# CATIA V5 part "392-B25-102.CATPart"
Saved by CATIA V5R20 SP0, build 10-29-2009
Part number: 392-B25-102
Definition: NONE
Nomenclature: 392-B25-102
Source: Unknown
Description: 392-B25-102
Bounding box of the stored display mesh (mm): x 0 to 102, y -12.355 to 12.355, z -12.25 to 12.064
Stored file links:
  C:\Users\Utente\Desktop\IO LAVORO\3D X SITO CF\X SITO\3D files 392B\392-B25-102.CATPart
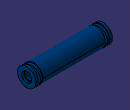
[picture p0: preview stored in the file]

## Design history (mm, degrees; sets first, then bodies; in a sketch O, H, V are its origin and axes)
Body1 "392-B25-102" (main body)
  Solid1: solid without history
